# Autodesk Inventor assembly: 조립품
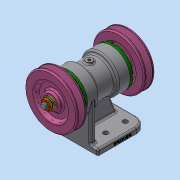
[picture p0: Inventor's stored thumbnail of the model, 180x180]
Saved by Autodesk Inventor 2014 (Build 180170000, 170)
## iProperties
Created: 2020-06
Part Number: 조립품
Document SubType Name: Assembly
Designer: kh
Author: kh
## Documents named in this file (11)
- C:\Users\kh\Desktop\700606V1028\조립품.iam
- C:\Users\kh\Desktop\700606V1028\본체.ipt
- C:\Users\kh\Desktop\700606V1028\축.ipt
- C:\Users\kh\Desktop\700606V1028\베어링 6204.ipt
- C:\Users\kh\Desktop\700606V1028\커버.ipt
- C:\Users\kh\Desktop\700606V1028\오일 실 20 32 5.ipt
- C:\Users\kh\Desktop\700606V1028\키 5x5x12.ipt
- C:\Users\kh\Desktop\700606V1028\V-벨트풀리.ipt
- C:\Users\kh\Desktop\700606V1028\스프링 와셔 10.ipt
- C:\Users\kh\Desktop\700606V1028\평면 와셔 10x21.ipt
- C:\Users\kh\Desktop\700606V1028\너트 M10.ipt
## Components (2 placed, 1 different names)
1. V-벨트풀리:1 — Mate:23, Mate:24, Flush:1, Mate:34
2. V-벨트풀리:2 — Mate:25, Mate:26, Flush:2, Mate:28
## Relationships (8: Mate 6, Flush 2)
- Mate:23: V-벨트풀리:1
- Mate:24: V-벨트풀리:1
- Flush:1: V-벨트풀리:1
- Mate:25: V-벨트풀리:2
- Mate:26: V-벨트풀리:2
- Flush:2: V-벨트풀리:2
- Mate:28: V-벨트풀리:2
- Mate:34: V-벨트풀리:1
